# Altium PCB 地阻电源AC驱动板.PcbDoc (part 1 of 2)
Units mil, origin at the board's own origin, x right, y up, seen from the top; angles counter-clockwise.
Board outline 3149.61 x 5118.11 mil, 2 copper layers (Top Layer, Bottom Layer); 154 components, 62 nets, 426 pads, 73 vias.
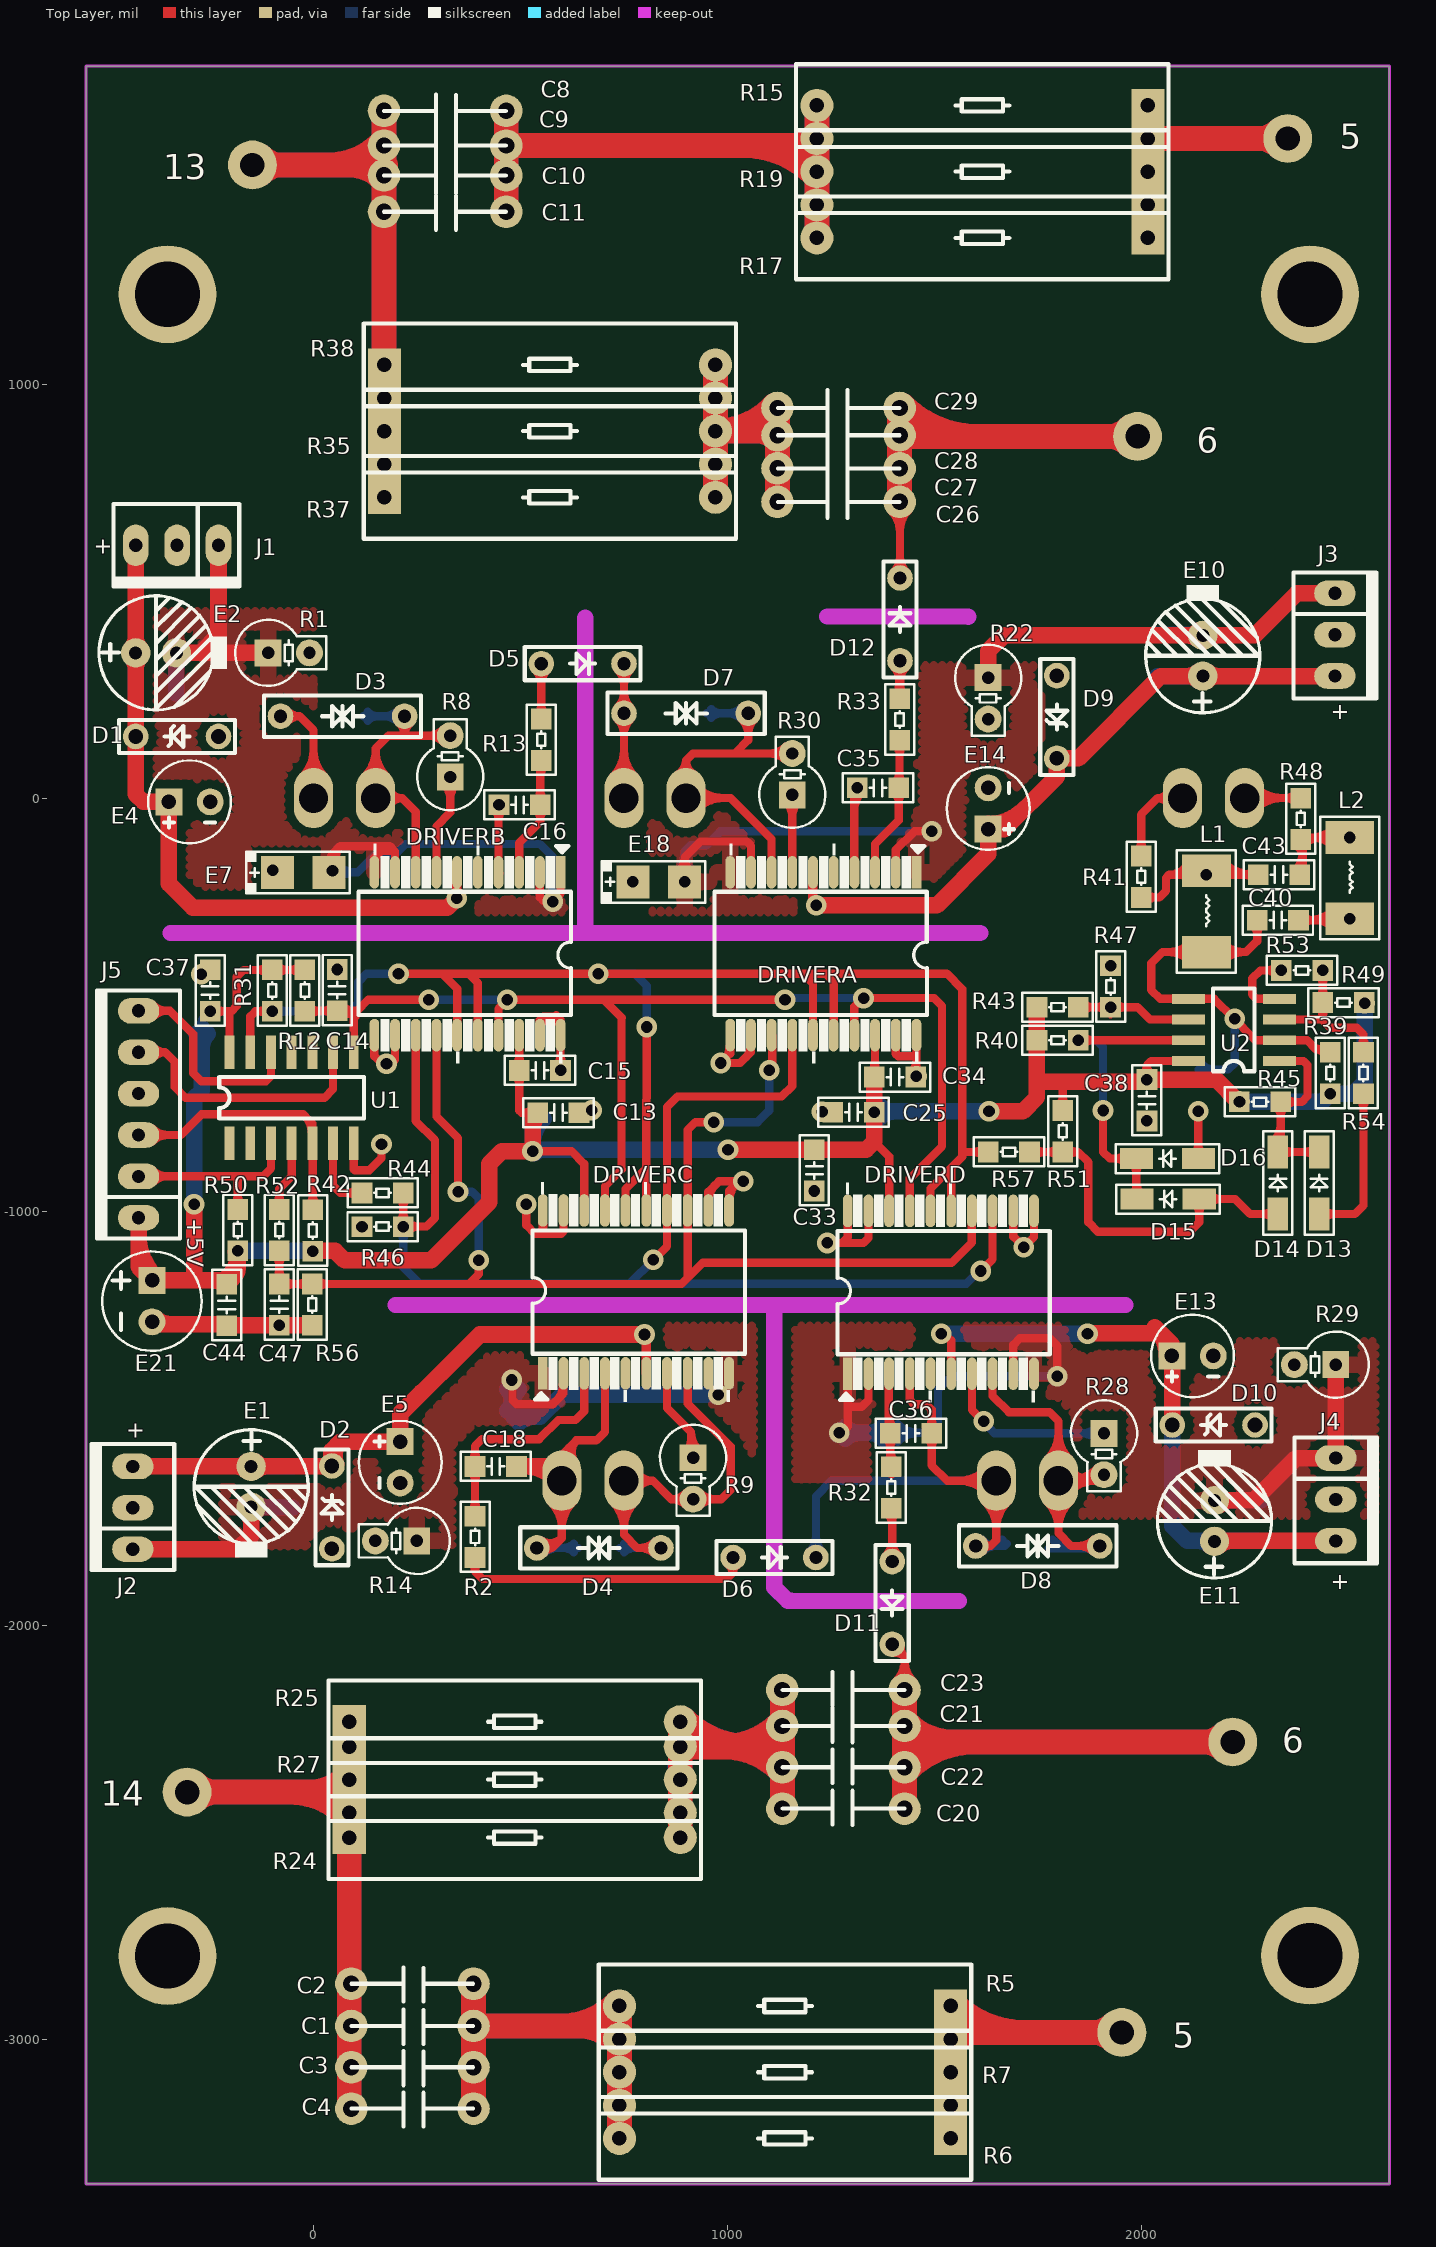
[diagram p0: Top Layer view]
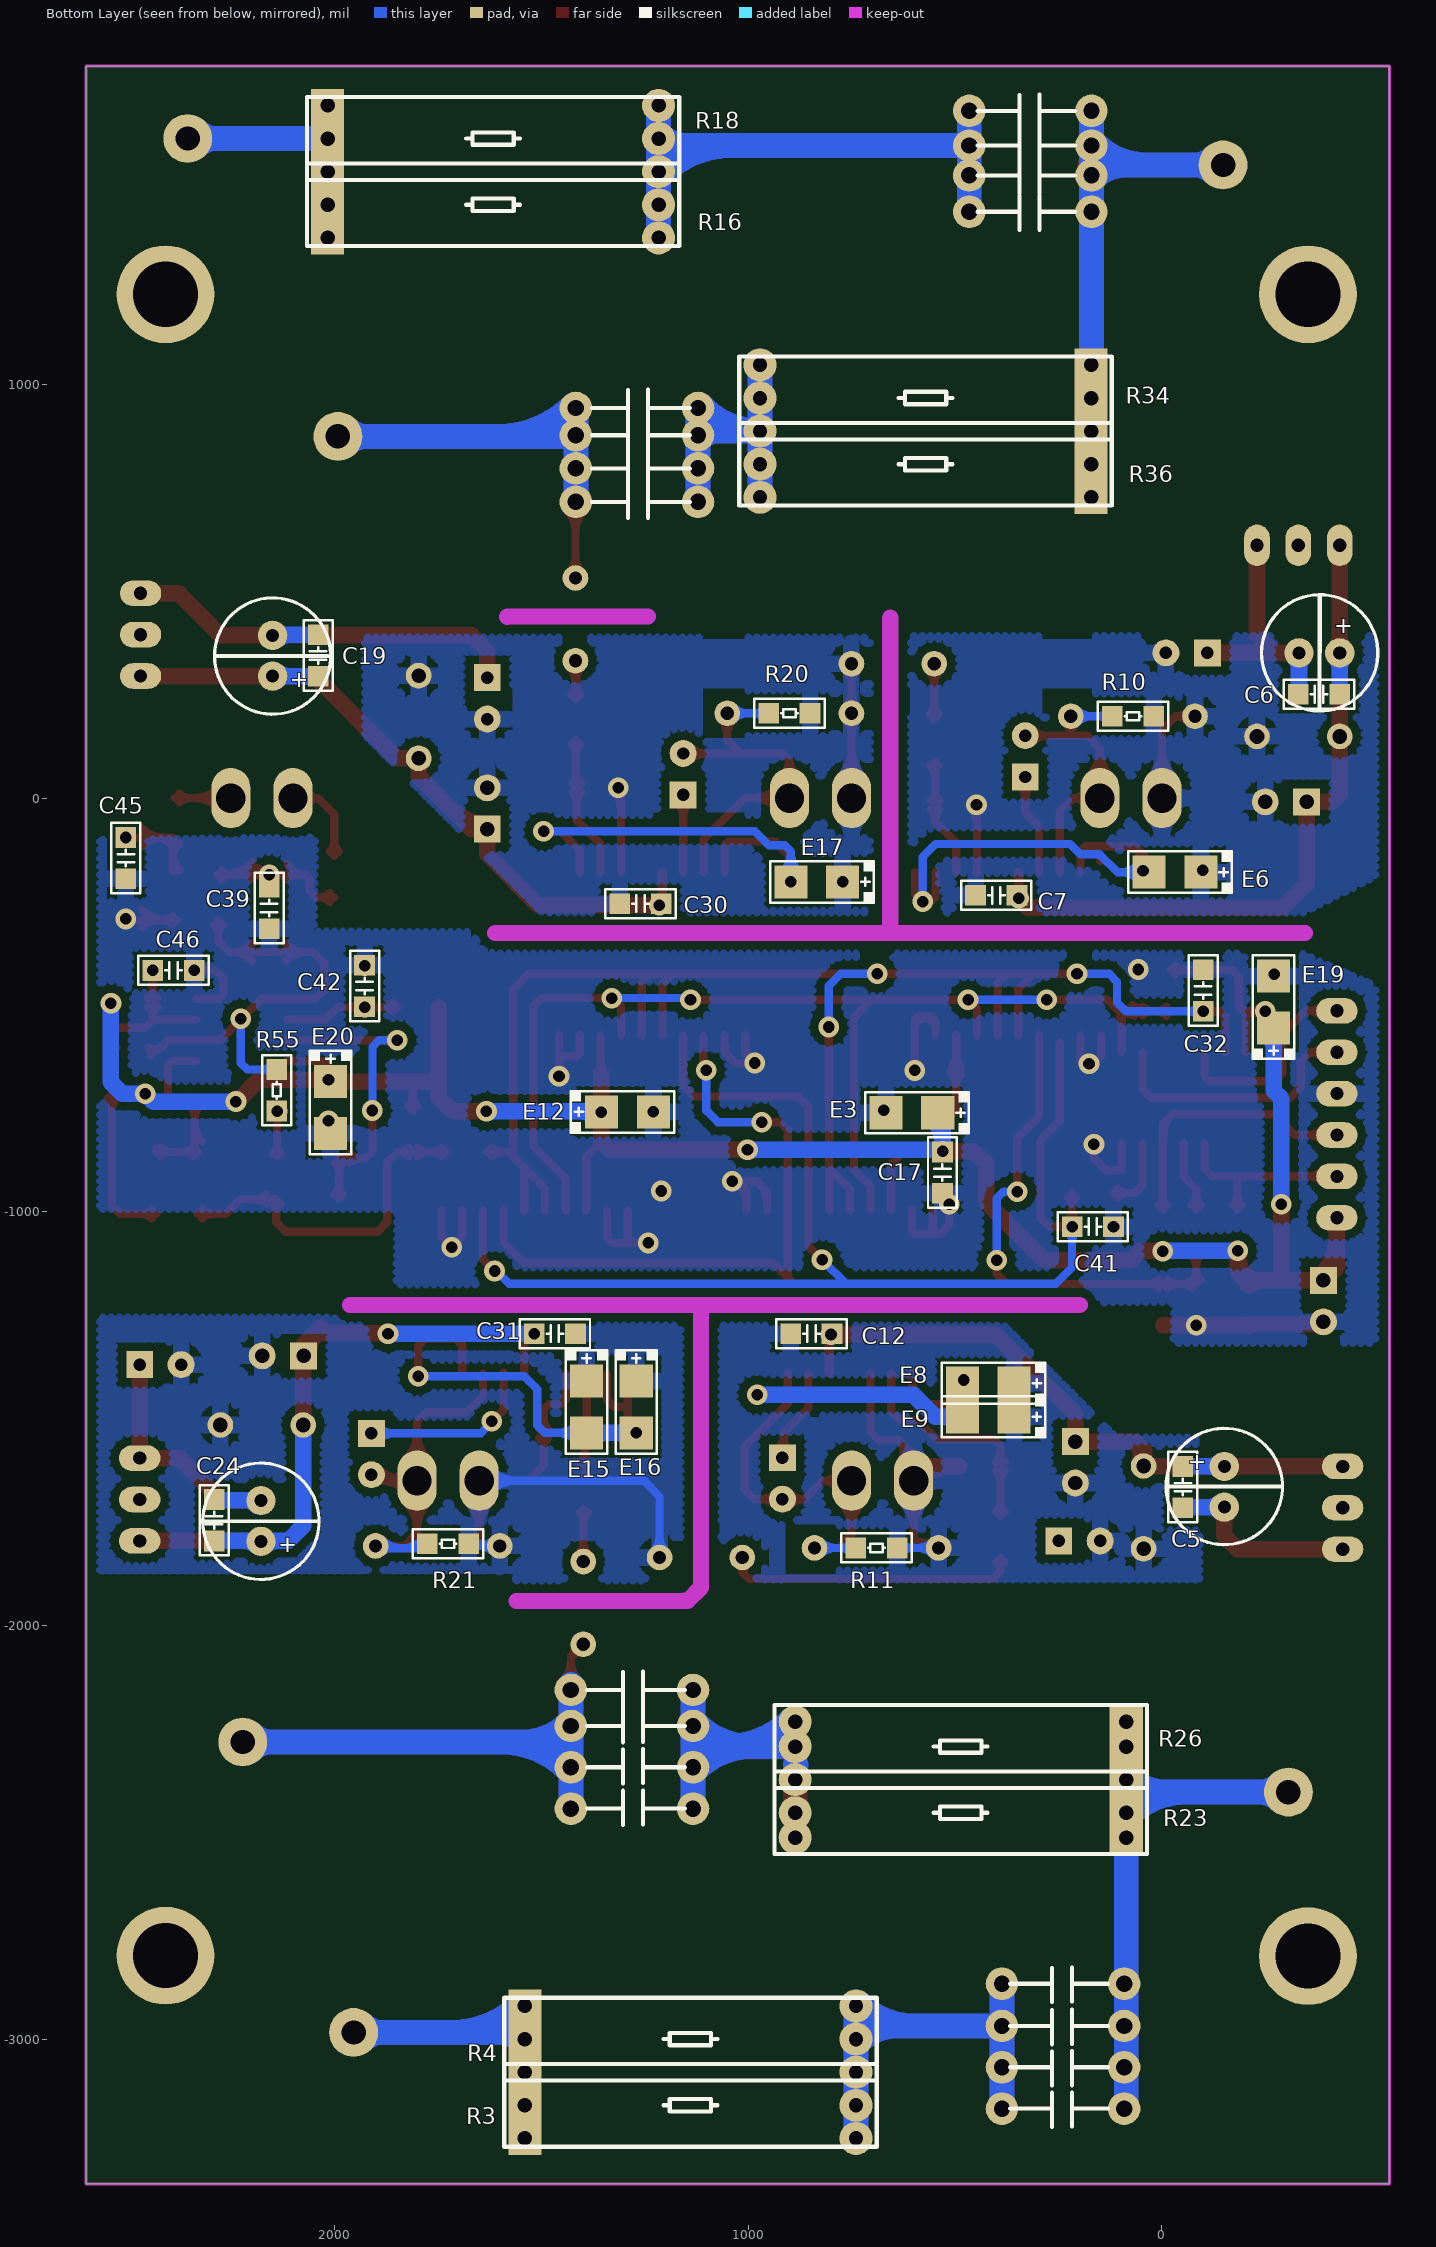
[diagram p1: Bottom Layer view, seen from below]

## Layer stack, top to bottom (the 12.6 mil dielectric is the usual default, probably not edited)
Top Layer: signal copper 1.4
Dielectric: dielectric 12.6, FR-4, Dk 4.8
Bottom Layer: signal copper 1.4

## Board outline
-549.72,-3349.01 2599.88,-3349.01 2599.88,1769.1 -549.72,1769.1

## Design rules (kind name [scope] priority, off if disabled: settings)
Clearance [All] p1: gap=12
ComponentClearance [All] p1 off: gap=10 collisioncheckmode=3 verticalgap=10
HoleSize [All] p1: absolutevalues=TRUE maxlimit=200 minlimit=20 maxpercent=80.000 minpercent=20.000
MaximumViaCount [All] p1: limit=1000
ParallelSegment [All] p1: limit=10000 gap=10
PolygonConnect [All] p1: connectstyle=Relief reliefconductorwidth=40 reliefentries=4 polygonreliefangle="90 Angle"
RoutingVias [All] p1: holewidth=28 width=50 viastyle="Through Hole" minholewidth=20 minwidth=30 maxholewidth=100 maxwidth=200
SolderMaskExpansion [All] p1: expansion=4
TestPointUsage [All] p1: valid=0 allowmultiple=FALSE
Testpoint [All] p1: side=15 testpointundercomponent=TRUE minsize=40 maxsize=100 preferedsize=60 minholesize=0 maxholesize=40 preferedholesize=32 testpointgrid=1 style=1023 order=0123456789
ViasUnderSMD [All] p1: allowed=TRUE
Width Width_1 [InNet('+5V')] p1: maxlimit=50 minlimit=10 preferedwidth=40
Width [All] p2: maxlimit=100 minlimit=10 preferedwidth=20 toplayer_prefwidth=40 minimp=50.000000 maximp=50.000000 favimp=50.000000
17 further rules are at their usual default settings.

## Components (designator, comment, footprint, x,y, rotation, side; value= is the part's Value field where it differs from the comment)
C1 "102/2KV" CP-7.5 91.28,-2967.16 r0 top
C2 "102/2KV" CP-7.5 91.28,-2865.16 r0 top
C3 "102/2KV" CP-7.5 91.28,-3067.16 r0 top
C4 "102/2KV" CP-7.5 91.28,-3167.16 r0 top
C5 "104" 0805C -50.72,-1715.16 r90 bottom
C6 "104" 0805C -329.72,250.99 r180 bottom
C7 "104" 0805C 350.28,-235.16 r0 bottom
C8 "102/2KV" CP-7.5 170.28,1660.84 r0 top
C9 "102/2KV" CP-7.5 170.28,1576.84 r0 top
C10 "102/2KV" CP-7.5 170.28,1504.84 r0 top
C11 "102/2KV" CP-7.5 170.28,1416.84 r0 top
C12 "104" 0805C 797.09,-1294.17 r0 bottom
C13 "104" 0805C 541.71,-760.35 r0 top
C14 "104" 0805C 57.09,-514.17 r90 top
C15 "104" 0805C 496.94,-658.16 r0 top
C16 "100P" 0805C 548.09,-16.17 r180 top
C17 "104" 0805C 530.28,-855.16 r270 bottom
C18 "100P" 0805C 390.28,-1615.16 r0 top
C19 "104" 0805C 2039.09,394.83 r270 bottom
C20 "102/2KV" CP-7.5 1428.28,-2442.16 r180 top
C21 "102/2KV" CP-7.5 1428.28,-2242.16 r180 top
C22 "102/2KV" CP-7.5 1428.28,-2342.16 r180 top
C23 "102/2KV" CP-7.5 1428.28,-2155.16 r180 top
C24 "104" 0805C 2290.28,-1795.16 r90 bottom
C25 "104" 0805C 1354.94,-759.16 r180 top
C26 "102/2KV" CP-7.5 1416.28,715.84 r180 top
C27 "102/2KV" CP-7.5 1416.28,796.84 r180 top
C28 "102/2KV" CP-7.5 1416.28,876.84 r180 top
C29 "102/2KV" CP-7.5 1416.28,942.84 r180 top
C30 "104" 0805C 1210.28,-255.16 r0 bottom
C31 "104" 0805C 1517.09,-1294.17 r180 bottom
C32 "104" 0805C -99.65,-515.16 r90 bottom
C33 "104" 0805C 1210.28,-849.49 r270 top
C34 "104" 0805C 1354.94,-674.16 r0 top
C35 "100P" 0805C 1413.94,24.84 r180 top
C36 "100P" 0805C 1393.94,-1535.16 r0 top
C37 "104" 0805C -249.72,-515.16 r90 top
C38 "104" 0805C 2013.94,-680.16 r270 top
C39 "104" 0805C 2157.54,-315.54 r90 bottom
C40 "104" 0805C 2280.28,-295.01 r0 top
C41 "30P" 0805C 217.05,-1035.59 r180 bottom
C42 "104" 0805C 1926.94,-504.16 r90 bottom
C43 "104" 0805C 2283.28,-185.16 r0 top
C44 "104" 0805C -209.72,-1175.16 r270 top
C45 "104" 0805C 2503.94,-95.16 r270 bottom
C46 "104" 0805C 2438.78,-416.43 r180 bottom
C47 "30P" 0805C -82.91,-1174.17 r270 top
D1 "IN4745" DIODE0.3-0.1 -334.72,154.99 r0 top
D2 "IN4745" DIODE0.3-0.1 50.28,-1709.01 r270 top
D3 "P6KE18CA" DIODE0.3-AC -79.91,197.83 r0 top
D4 "P6KE18CA" DIODE0.3-AC 539.61,-1812.05 r0 top
D5 "ER34-10" DIODE0.2 750.28,324.84 r180 top
D6 "ER34-10" DIODE0.2 1213.94,-1835.16 r180 top
D7 "P6KE18CA" DIODE0.3-AC 750.28,204.84 r0 top
D8 "P6KE18CA" DIODE0.3-AC 1600.15,-1807.2 r0 top
D9 "IN4745" DIODE0.3-0.1 1790.28,190.99 r90 top
D10 "IN4745" DIODE0.3-0.1 2170.28,-1509.01 r0 top
D11 "ER34-10" DIODE0.2 1398.28,-2045.01 r90 top
D12 "ER34-10" DIODE0.2 1417.28,531.84 r270 top
D13 "IN4148" DIODE-SMD0.15 2430.28,-855.16 r270 top
D14 "IN4148" DIODE-SMD0.15 2330.28,-855.16 r270 top
D15 "IN4148" DIODE-SMD0.15 1990.28,-969.01 r0 top
D16 "IN4148" DIODE-SMD0.15 1988.28,-871.16 r0 top
DRIVERA "IGBT driver" SOP20-7.6-1.27 1273.94,-375.16 r270 top locked
DRIVERB "IGBT driver" SOP20-7.6-1.27 413.94,-375.15 r270 top locked
DRIVERC "IGBT driver" SOP20-7.6-1.27 737.09,-1194.17 r90 top locked
DRIVERD "IGBT driver" SOP20-7.6-1.27 1473.94,-1195.16 r90 top locked
E1 "100u/50V" E2.5-7 -150.72,-1615.16 r270 top
E2 "100u/50V" E2.5-7 -429.72,350.99 r0 top
E3 "10uF/16V" 1210E 541.69,-760.35 r0 bottom
E4 "10u/50v" E0.1/R0.1 -349.72,-9.01 r0 top
E5 "10u/50v" E0.1/R0.1 209.28,-1555.16 r270 top
E6 "10uF/16V" 1210E -94.09,-178.98 r0 bottom
E7 "10uF/16V" 1210E -87.4,-179.96 r0 top
E8 "10uF/16V" 1210E 357.09,-1414.17 r0 bottom
E9 "10uF/16V" 1210E 357.28,-1495.16 r0 bottom
E10 "100u/50V" E2.5-7 2148.94,294.84 r90 top
E11 "100u/50V" E2.5-7 2177.28,-1796.01 r90 top
E12 "10uF/16V" 1210E 1353.94,-758.16 r180 bottom
E13 "10u/50v" E0.1/R0.1 2074.28,-1348.01 r0 top
E14 "10u/50v" E0.1/R0.1 1630.28,-75.16 r90 top
E15 "10uF/16V" 1210E 1390.28,-1409.01 r270 bottom
E16 "10uF/16V" 1210E 1270.28,-1409.01 r270 bottom
E17 "10uF/16V" 1210E 771.61,-202.36 r0 bottom
E18 "10uF/16V" 1210E 771.61,-202.36 r0 top
E19 "10uF/16V" 1210E -269.72,-555.16 r90 bottom
E20 "10uF/16V" 1210E 2008.95,-685.14 r270 bottom
E21 "100u/25V" E0.1/R0.12 -390.35,-1165.63 r270 top
J1 "AC驱动电源" CON03 -229.72,610.99 r180 top
J2 "AC驱动电源" CON03 -436.72,-1815.01 r90 top
J3 "AC驱动电源" CON03 2468.28,494.99 r270 top
J4 "AC驱动电源" CON03 2470.28,-1595.01 r270 top
J5 "AC-全桥" CON06 -422.91,-1014.17 r90 top
L1 "10uH" L10UH-SMD 2157.54,-175.54 r270 top
L2 "10uH" L10UH-SMD 2503.94,-95.16 r270 top
R1 "510/1W" RES0.1-1W-STAND -109.72,350.99 r0 top
R2 "510/1W" RES0.1-1W-STAND 249.28,-1795.16 r180 top
R3 "51/2W" RES0.8-2W 1539.28,-3159.01 r180 bottom
R4 "51/2W" RES0.8-2W 1539.28,-2999.01 r180 bottom
R5 "51/2W" RES0.8-2W 1539.28,-2919.01 r180 top
R6 "51/2W" RES0.8-2W 1539.28,-3239.01 r180 top
R7 "51/2W" RES0.8-2W 1539.28,-3079.01 r180 top
R8 "10/1W" RES0.1-1W-STAND 330.28,50.99 r90 top
R9 "10/1W" RES0.1-1W-STAND 917.09,-1594.17 r270 top
R10 "5.1K" 0805R 20.09,197.83 r0 bottom
R11 "5.1K" 0805R 639.61,-1812.05 r0 bottom
R12 "5.1K" 0805R -20.91,-515.17 r90 top
R13 "1.2K" 0805R 550.28,190.99 r270 top
R14 "1.2K" 0805R 390.28,-1835.16 r90 top
R15 "51/2W" RES0.8-2W 2016.28,1673.84 r180 top
R16 "51/2W" RES0.8-2W 2016.28,1433.84 r180 bottom
R17 "51/2W" RES0.8-2W 2016.28,1353.84 r180 top
R18 "51/2W" RES0.8-2W 2016.28,1593.84 r180 bottom
R19 "51/2W" RES0.8-2W 2016.28,1513.84 r180 top
R20 "5.1K" 0805R 850.28,204.84 r0 bottom
R21 "5.1K" 0805R 1675.15,-1802.2 r0 bottom
R22 "510/1W" RES0.1-1W-STAND 1630.28,290.99 r270 top
R23 "51/2W" RES0.8-2W 86.28,-2452.01 r0 bottom
R24 "51/2W" RES0.8-2W 86.28,-2512.01 r0 top
R25 "51/2W" RES0.8-2W 86.28,-2232.01 r0 top
R26 "51/2W" RES0.8-2W 86.28,-2292.01 r0 bottom
R27 "51/2W" RES0.8-2W 86.28,-2372.01 r0 top
R28 "10/1W" RES0.1-1W-STAND 1910.28,-1535.16 r270 top
R29 "510/1W" RES0.1-1W-STAND 2470.28,-1369.01 r180 top
R30 "10/1W" RES0.1-1W-STAND 1156.94,7.84 r90 top
R31 "5.1K" 0805R -99.65,-515.16 r90 top
R32 "1.2K" 0805R 1396.28,-1716.16 r90 top
R33 "1.2K" 0805R 1416.28,239.84 r270 top
R34 "51/2W" RES0.8-2W 171.28,966.84 r0 bottom
R35 "51/2W" RES0.8-2W 171.28,886.84 r0 top
R36 "51/2W" RES0.8-2W 171.28,806.84 r0 bottom
R37 "51/2W" RES0.8-2W 171.28,726.84 r0 top
R38 "51/2W" RES0.8-2W 171.28,1046.84 r0 top
R39 "15K" 0805R 2457.09,-714.17 r90 top
R40 "5.1K" 0805R 1848.09,-585.17 r180 top
R41 "0" 0805R 2000,-140 r270 top
R42 "5.1K" 0805R -1.72,-995.01 r270 top
R43 "15K" 0805R 1748.09,-505.17 r0 top
R44 "180" 0805R 117.09,-954.17 r0 top
R45 "5.1K" 0805R 2337.09,-734.17 r180 top
R46 "15K" 0805R 117.05,-1035.59 r0 top
R47 "470" 0805R 1926.09,-505.17 r90 top
R48 "0" 0805R 2385.43,0 r270 top
R49 "3K" 0805R 2438.78,-494.17 r0 top
R50 "5.1K" 0805R -182.91,-994.17 r270 top
R51 "5.1K" 0805R 1810.28,-755.16 r270 top
R52 "180" 0805R -82.91,-994.17 r270 top
R53 "30K" 0805R 2338.78,-416.43 r0 top
R54 "30K" 0805R 2537.09,-714.17 r90 top
R55 "30K" 0805R 2139.28,-656.01 r270 bottom
R56 "15K" 0805R -2.91,-1274.17 r90 top
R57 "5.1K" 0805R 1730.28,-855.16 r180 top
U1 "74HC04" SOP14 -202.91,-834.17 r90 top
U2 "LM358" SOP08 2333.94,-635.16 r180 top

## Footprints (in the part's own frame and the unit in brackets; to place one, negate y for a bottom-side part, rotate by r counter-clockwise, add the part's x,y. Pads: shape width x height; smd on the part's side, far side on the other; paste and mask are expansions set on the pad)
0805C [mil]
  rect 50x50 smd: 1(0,0) 2(100,0)
  silkscreen extent -35,-35 135,35
0805R [mil]
  rect 50x50 smd: 1(0,0) 2(100,0)
  silkscreen extent -35,-35 135,35
1210E [mil]
  rect 80x80 smd: 1(0,0) 2(125,0)
  silkscreen extent -75,-50 175,50
CON03 [mil]
  oval 62x100 hole 32: 1(0,0) 2(100,0) 3(200,0)
  silkscreen extent -50,-100 254,100
CON06 [mil]
  oval 62x100 hole 32: 1(0,0) 2(100,0) 3(200,0) 4(300,0) 5(400,0) 6(500,0)
  silkscreen extent -50,-100 549,100
CP-7.5 [mm]
  round 2 hole 1: 1(0,0) 2(7.5,0)
  silkscreen extent 0,-1.1 7.47,1
DIODE0.2 [mil]
  round 62 hole 32: 1(200,0) 2(0,0)
  silkscreen extent -40,-40 240,40
DIODE0.3-0.1 [mm]
  round 1.575 hole 0.9: 1(2.667,-0.152) 2(-2.413,-0.152)
  silkscreen extent -3.43,-1.17 3.68,0.86
DIODE0.3-AC [mil]
  round 62 hole 32: 1(0,0) 2(300,0)
  silkscreen extent -40,-50 340,50
DIODE-SMD0.15 [mil]
  rect 80x50 smd: 1(150,0) 2(0,0)
  silkscreen extent -50,-35 200,35
E0.1/R0.1 [mil]
  rect 65x65 hole 35: 1(0,0)
  round 65 hole 35: 2(100,0)
  silkscreen extent -50,-100 150,100
E0.1/R0.12 [mil]
  rect 65x65 hole 35: 1(0,0)
  round 65 hole 35: 2(100,0)
  silkscreen extent -70,-120 170,120
E2.5-7 [mm]
  round 1.8 hole 0.8: 1(0,0) 2(2.5,0)
  silkscreen extent -2.25,-3.5 5.6,3.5
L10UH-SMD [mm] "贴片电感"
  rect 2x3 smd: 1(0,0) 2(5,0)
  silkscreen extent -1.27,-1.8 6.26,1.8
RES0.1-1W-STAND [mil]
  rect 65x65 hole 30: 1(0,0)
  round 65 hole 30: 2(100,0)
  silkscreen extent -80,-80 140,80
RES0.8-2W [mil]
  rect 80x80 hole 35: 1(0,0)
  round 80 hole 35: 2(800,0)
  silkscreen extent -50,-100 850,100
SOP08 [mil]
  rect 80x24 smd: 1(0,0) 2(0,-50) 3(0,-100) 4(0,-150) 5(220,-150) 6(220,-100) 7(220,-50) 8(220,0)
  silkscreen extent 60,-175 160,25
SOP14 [mil]
  rect 80x24 smd: 1(0,0) 2(0,-50) 3(0,-100) 4(0,-150) 5(0,-200) 6(0,-250) 7(0,-300) 8(220,-300) 9(220,-250) 10(220,-200) 11(220,-150) 12(220,-100) 13(220,-50) 14(220,0)
  silkscreen extent 60,-325 160,25
SOP20-7.6-1.27 [mm]
  rect 2x0.6 smd: 1(-4.978,4.648)
  oval 2x0.6 smd: 2(-4.978,3.378) 3(-4.978,2.108) 4(-4.978,0.838) 5(-4.978,-0.432) 6(-4.978,-1.702) 7(-4.978,-2.972) 8(-4.978,-4.242) 9(-4.978,-5.512) 10(-4.978,-6.782) 11(5.022,-6.782) 12(5.022,-5.512) 13(5.022,-4.242) 14(5.022,-2.972) 15(5.022,-1.702) 16(5.022,-0.432) 17(5.022,0.838) 18(5.022,2.108) 19(5.022,3.378) 20(5.022,4.648)
  silkscreen extent -6.74,-7.75 6.77,5.29

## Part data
C1 C2 C3 C4 C8 C9 C10 C11 C20 C21 C22 C23 C26 C27 C28 C29: library part Cap2, "CBB电容"
C5 C6 C7 C12 C13 C14 C15 C16 C17 C18 C19 C24 C25 C30 C31 C32 C33 C34 C35 C36 C37 C38 C39 C40 C41 C42 C43 C44 C45 C46 C47: library part Cap, "贴片电容"
D1 D2 D9 D10: library part Diode5, "贴片稳压管"
D3 D4 D7 D8: library part "D TVS", "TVS管"
D5 D6 D11 D12: library part Diode2, "贴片二极管"
D13 D14: library part DIODE7
D15 D16: library part Diode1, "二极管"
DRIVERA: "单个IGBT驱动"
E1 E2 E4 E5 E10 E11 E13 E14: library part "Cap Pol", "电解电容"
E3: library part "Cap Pol", "贴片电解电容"
E6 E7 E8 E9 E12 E15 E16 E17 E18 E19 E20 E21: library part "Cap Pol3", "贴片电解电容"
J1 J2 J3 J4: library part CON3, "接插件，3针"
J5: library part CON6, "接插件，6针"
L1 L2: library part Inductor1, "贴片电感"
R1 R2 R8 R9 R10 R11 R12 R13 R14 R20 R21 R28 R29 R30 R31 R32 R33 R39 R40 R41 R42 R43 R44 R45 R46 R47 R48 R49 R50 R51 R52 R53 R54 R55 R56 R57: library part RES2, "贴片电阻"
R3 R4 R5 R6 R7 R15 R16 R17 R18 R19 R22 R23 R24 R25 R26 R27 R34 R35 R36 R37 R38: library part RES1, "金属膜电阻"
U1: "6通道反相器"
U2: "双运放"

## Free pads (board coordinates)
  round 118.11 hole 59.06: 0(1953.28,-2983.01) 0(2221.28,-2281.01) 0(2354.28,1593.99) 1(1991.28,873.99) 2(-305.72,-2402.16) 3(-147.72,1529.99)
  oval 94.49x145.67 hole 70.87: 0(2250,0) 1(600,-1649.61) 2(750,-1649.61) 3(1650,-1649.61) 4(1800,-1649.61) 8(2100,0) 9(900,0) 10(750,0) 11(150,0) 12(0,0)
  round 236.22 hole 157.48: 3(-352.87,-2798.31) 3(-352.87,1217.44) 3(2407.95,-2797.32) 3(2407.95,1217.44)

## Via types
v1: diameter 50, hole 28, Top Layer to Bottom Layer, 54 vias
v2: diameter 50, hole 27.99, Top Layer to Bottom Layer, 19 vias

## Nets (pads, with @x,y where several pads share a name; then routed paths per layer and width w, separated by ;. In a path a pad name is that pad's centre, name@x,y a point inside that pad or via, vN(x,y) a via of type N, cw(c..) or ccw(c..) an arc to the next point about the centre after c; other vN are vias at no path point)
+5V: C13.1 C15.1 C17.1 C25.1 C33.1 C34.1 C37.1 C38.1 C44.1 DRIVERA.18 DRIVERB.18 DRIVERC.18 DRIVERD.18 E3.1 E12.1 E19.1 E20.1 E21.1 J5.1 R12.2 R31.2 R39.1 R40.2 R42.2 R43.1 R45.2 R49.2 R50.2 R51.1 U1.14 U2.8 | length 7444.8
  Top Layer w20: E21.1@-377.85,-1153.13 E21.1@-375.35,-1155.63 ; v2(-249.72,-515.16) -213.87,-515.16 ; C37.1@-239.04,-525.69 cw(c-213.88,-550.49) -213.88,-515.16 ; C37.1@-239.04,-504.63 ccw(c-213.88,-479.82) -213.88,-515.16 ; U1.14@-202.91,-614.17 -202.91,-526.12 -213.87,-515.16 ; R31.2@-110.25,-425.76 ccw(c-135.86,-451.37) -135.86,-415.16 ccw(c-135.86,-378.94) R31.2@-110.25,-404.55 ; R31.2@-89.04,-425.76 cw(c-63.43,-451.37) -63.43,-415.16 cw(c-63.43,-378.94) R31.2@-89.04,-404.55 ; -57.16,-415.16 cw(c-57.16,-451.42) R12.2@-31.52,-425.78 ; -57.09,-415.16 ccw(c-57.09,-379) R12.2@-31.52,-404.57 ; R12.2@-20.91,-415.17 R31.2@-99.65,-415.16 -168.87,-415.16 -185.72,-432.01 -185.72,-502.31 -198.57,-515.16 -213.87,-515.16 ; C15.1@486.33,-668.76 cw(c460.72,-694.37) 496.94,-694.37 cw(c533.15,-694.37) C15.1@507.54,-668.76 ; C15.1@486.33,-647.55 ccw(c460.72,-621.94) 496.94,-621.94 ccw(c533.15,-621.94) C15.1@507.54,-647.55 ; C15.1@493.94,-661.16 C15.1@496.94,-658.16 ; DRIVERB.18@496.94,-572.85 C15.1@496.94,-658.16 ; v1(529.28,-853.16) 623.43,-853.16 654.09,-883.82 DRIVERC.18@654.09,-996.47 ; C13.1@531.1,-770.95 ccw(c505.5,-796.56) 505.5,-760.35 ccw(c505.5,-724.13) C13.1@531.1,-749.74 ; C13.1@541.71,-760.35 502.47,-760.35 496.94,-754.82 C15.1@496.94,-658.16 ; C34.1@1344.33,-663.55 ccw(c1313.9,-633.12) 1356.94,-633.12 ; 1354.94,-830.16 1390.94,-866.16 DRIVERD.18@1390.94,-997.46 ; C34.1@1354.94,-674.16 C34.1@1356.94,-672.16 ; C34.1@1356.94,-674.16 C34.1@1356.94,-672.16 ; 1356.94,-642.77 ccw(c1386.32,-642.77) C34.1@1365.54,-663.55 ; DRIVERA.18@1356.94,-572.86 C34.1@1356.94,-672.16 ; R51.1@1799.67,-744.55 ccw(c1774.06,-718.94) 1810.28,-718.94 ccw(c1846.49,-718.94) R51.1@1820.88,-744.55 ; 1806.3,-685.14 1810.28,-689.12 R51.1@1810.28,-755.16 ; C38.1@2003.67,-669.22 ccw(c1981.39,-645.5) 2013.94,-645.5 ; C38.1@2017.28,-676.82 v1(2013.94,-680.16) 2013.94,-645.5 ; C38.1@2024.2,-669.22 cw(c2046.48,-645.5) 2013.94,-645.5 ; U2.8@2113.94,-635.16 2024.28,-635.16 2013.94,-645.5
  Top Layer w40: -422.91,-1056.85 ccw(c-281.57,-1056.85) E21.1@-381.52,-1156.79 ; J5.1@-422.91,-1014.17 -422.91,-1132.99 -390.35,-1165.55 -288.72,-1165.55 ; v2(-288.72,-981.16) -288.72,-1165.55 ; -244.99,-1165.55 cw(c-244.99,-1210.42) C44.1@-213.26,-1178.69 ; C44.1@-213.26,-1171.62 ccw(c-286.52,-1098.36) R50.2@-182.91,-1098.36 ; C44.1@-211.28,-1170.4 ccw(c-224.05,-1131.3) -182.91,-1131.3 ; C44.1@-204.72,-1175.16 cw(c-151.5,-1175.16) -189.13,-1137.52 ; -198.6,-1146.99 ccw(c-232.66,-1112.93) R50.2@-187.59,-1095.94 ; v1(-182.91,-1094.17) -182.91,-1131.3 ; R42.2@4.29,-1094.17 52.05,-1094.17 75.08,-1117.2 283.94,-1117.2 424.28,-976.87 424.28,-884.16 455.28,-853.16 v1(529.28,-853.16) 529.28,-772.78 C13.1@541.71,-760.35 ; C15.1@496.94,-658.16 C15.1@500.47,-661.69 ; 529.28,-802.43 cw(c583.8,-802.43) C13.1@545.24,-763.88 ; v1(1001.46,-849.49) C33.1@1210.28,-849.49 1335.61,-849.49 1354.94,-830.16 v1(1354.94,-759.16) C34.1@1354.94,-674.16 ; v1(1632.36,-756.97) 1714.24,-756.97 1748.09,-723.12 R40.2@1748.09,-585.17 ; R40.2@1747.4,-585.17 1747.4,-505.86 R43.1@1748.09,-505.17 ; 1748.22,-685.14 1806.3,-685.14 C38.1@2008.95,-685.14 ; v1(2013.94,-680.16) 2181.61,-680.16 2234.43,-732.97 2237.09,-732.97 2237.68,-732.97 2238.29,-732.97 R45.2@2240.63,-735.31 ; -288.72,-1165.55 -217.16,-1165.55 -182.91,-1131.3
  Bottom Layer w20: E19.1@-269.72,-555.16 -269.72,-535.16 v2(-249.72,-515.16)
  Bottom Layer w40: v2(-288.72,-981.16) -288.72,-726.16 -269.72,-707.16 E19.1@-269.72,-555.16 ; E19.1@-283.87,-569.3 cw(c-318.01,-603.44) -269.72,-603.44 cw(c-221.44,-603.44) E19.1@-255.58,-569.3 ; v1(-182.91,-1094.17) -2.56,-1094.17 v1(-1.72,-1095.01) ; C17.1@529.28,-838.62 cw(c619.95,-838.62) E3.1@555.84,-774.5 ; C17.1@530.28,-855.16 529.28,-854.16 v1(529.28,-853.16) 529.28,-772.78 E3.1@541.69,-760.35 ; C17.1@533.81,-858.69 cw(c556.03,-880.91) 556.03,-849.49 ; C17.1@535.95,-849.49 v1(1001.46,-849.49) v1@997.79,-853.16 ; v1(1354.94,-759.16) 1357.13,-756.97 v1(1632.36,-756.97) ; E12.1@1368.08,-772.3 cw(c1405.09,-809.31) 1405.09,-756.97 ; E12.1@1368.08,-744.01 ccw(c1399.35,-712.74) 1399.35,-756.97 ; v1(2237.68,-733.35) 2437.91,-733.35 v2(2457.09,-714.17) 2512.76,-714.17 2539.84,-687.09 v2(2539.84,-496.14)
+24V1: C19.2 C30.1 D9.2 DRIVERA.6 E10.1 E14.1 J3.3 | length 2016.8
  Top Layer w23: v1@1205.2,-268.78 1206.94,-267.04 1206.94,-259.16 DRIVERA.6@1206.94,-179.16
  Top Layer w40: v1(1214.82,-259.16) 1506.28,-259.16 1630.28,-135.16 E14.1@1630.28,-75.16 1669.09,-75.16 1796.26,52.01 D9.2@1796.26,95.99 1848.28,95.99 2047.13,294.84 E10.1@2148.94,294.84 ; E14.1@1630.28,-62.66 ccw(c1630.28,61.24) 1717.88,-26.37 ; E10.1@2138.02,283.93 ccw(c2111.68,257.58) 2111.68,294.84 ccw(c2111.68,332.1) E10.1@2138.02,305.76 ; E10.1@2149.09,294.99 J3.3@2468.28,294.99 ; E10.1@2159.85,283.93 cw(c2186.56,257.22) 2186.56,294.99 ; E10.1@2159.85,305.76 ccw(c2185.83,331.74) 2185.83,294.99
  Bottom Layer w40: C19.2@2039.09,294.83 E10.1@2148.94,294.84 ; E10.1@2138.02,283.93 ccw(c2111.68,257.58) 2111.68,294.84 ccw(c2111.68,332.1) E10.1@2138.02,305.76
+24V2: C6.2 C7.1 D1.2 DRIVERB.6 E2.1 E4.1 J1.3 | length 1958.8
  Top Layer w23: v1(345.95,-242.2) 345.95,-180.15 DRIVERB.6@346.94,-179.15 ; v1@346.94,-250.09 v1@349.32,-252.46
  Top Layer w40: E2.1@-440.64,340.08 cw(c-466.98,313.73) -429.72,313.73 cw(c-392.47,313.73) E2.1@-418.81,340.08 ; E2.1@-440.64,361.91 ccw(c-466.98,388.25) -429.72,388.25 ccw(c-392.47,388.25) E2.1@-418.81,361.91 ; J1.3@-429.72,610.99 E2.1@-429.72,350.99 D1.2@-429.72,149.01 -429.72,8.99 -411.72,-9.01 E4.1@-349.72,-9.01 -349.72,-206.84 -291.72,-264.84 323.31,-264.84 v1(345.95,-242.2)
  Bottom Layer w40: E2.1@-440.64,340.08 cw(c-466.98,313.73) -429.72,313.73 cw(c-392.47,313.73) E2.1@-418.81,340.08 ; C6.2@-429.72,250.99 E2.1@-429.72,350.99
+24V3: C5.2 C12.1 D2.2 DRIVERC.6 E1.1 E5.1 J2.3 | length 1932.5
  Top Layer w23: v1(799.69,-1296.34) 804.09,-1300.74 DRIVERC.6@804.09,-1390.17
  Top Layer w40: J2.3@-436.57,-1615.16 E1.1@-150.72,-1615.16 D2.2@43.14,-1615.16 ; E1.1@-161.64,-1626.07 ccw(c-187.98,-1652.42) -187.98,-1615.16 ccw(c-187.98,-1577.9) E1.1@-161.64,-1604.24 ; E1.1@-139.81,-1626.07 cw(c-113.47,-1652.42) -113.47,-1615.16 cw(c-113.47,-1577.9) E1.1@-139.81,-1604.24 ; D2.2@43.14,-1614.01 43.14,-1577.14 65.13,-1555.16 ; D2.2@54.43,-1609.74 cw(c100.36,-1590.4) 65.12,-1555.16 ; 260.28,-1436.16 209.28,-1487.16 209.28,-1489.16 ; v1(799.69,-1296.34) 402.09,-1296.34 209.28,-1489.16 ; 65.13,-1555.16 E5.1@209.28,-1555.16 209.28,-1489.16
  Bottom Layer w40: E1.1@-150.72,-1615.16 C5.2@-50.72,-1615.16 ; E1.1@-139.81,-1626.07 cw(c-113.47,-1652.42) -113.47,-1615.16 cw(c-113.47,-1577.9) E1.1@-139.81,-1604.24
+24V4: C24.1 C31.1 D10.2 DRIVERD.6 E11.1 E13.1 J4.3 | length 1821.9
  Top Layer w20: v1@1522.13,-1291.42 1540.94,-1310.23 DRIVERD.6@1540.94,-1391.16
  Top Layer w40: v1@1871.49,-1293.01 2047.28,-1293.01 2074.28,-1320.01 E13.1@2074.28,-1348.01 ; 2033.28,-1279.01 cw(c1964.48,-1347.81) E13.1@2061.78,-1347.98 ; E13.1@2065.44,-1356.85 cw(c2041.68,-1380.6) 2075.28,-1380.6 ; D10.2@2075.28,-1514.99 E13.1@2075.28,-1349.01 ; E11.1@2177.28,-1796.01 2178.28,-1795.01 J4.3@2470.28,-1795.01 ; E11.1@2188.19,-1806.92 cw(c2216.95,-1835.68) 2216.95,-1795.01
  Bottom Layer w23: v1@1863.66,-1287.48 v1@1867.6,-1291.42
  Bottom Layer w40: C31.1@1524.87,-1294.16 v1(1870.34,-1294.16) ; D10.2@2075.28,-1514.99 2075.28,-1759.01 2111.43,-1795.16 2177.28,-1795.16 C24.1@2280.28,-1795.16 ; 2137.96,-1795.16 cw(c2137.96,-1835.32) E11.1@2166.36,-1806.92 ; E11.1@2188.19,-1806.92 cw(c2216.59,-1835.32) 2216.59,-1795.16
  other v1: 1517.09,-1294.17
/FLT: C32.1 DRIVERA.15 DRIVERA.16 DRIVERB.15 DRIVERB.16 DRIVERC.15 DRIVERC.16 DRIVERD.15 DRIVERD.16 R31.1 R57.2 U1.13 | length 4227.9
  Top Layer w20: U1.13@-152.91,-614.17 -152.91,-527.5 -140.57,-515.16 v1(-99.65,-515.16) ; R31.1@-110.25,-525.76 ccw(c-135.86,-551.37) -135.86,-515.16 ccw(c-135.86,-478.94) R31.1@-110.25,-504.55 ; v1(205.28,-424.16) 314.28,-424.16 ; DRIVERB.15@346.94,-572.85 346.94,-460.5 314.28,-427.83 314.28,-424.16 ; DRIVERB.16@396.94,-572.85 396.94,-446.82 374.28,-424.16 ; DRIVERC.16@754.09,-996.47 754.09,-944.51 798.44,-900.16 804.09,-900.16 ; DRIVERC.15@804.09,-996.47 804.09,-900.16 ; v2(805.28,-553.16) 804.09,-900.16 ; DRIVERA.15@1206.94,-572.86 1206.94,-447.82 1183.28,-424.16 ; DRIVERA.16@1256.94,-572.86 1256.94,-443.82 1237.28,-424.16 ; DRIVERD.16@1490.94,-997.46 1490.94,-943.5 1540.94,-893.5 ; DRIVERD.15@1540.94,-997.46 1540.94,-893.5 ; 1568.4,-855.16 R57.2@1630.28,-855.16 ; R57.2@1619.67,-865.76 ccw(c1594.06,-891.37) 1594.06,-855.16 ccw(c1594.06,-818.94) R57.2@1619.67,-844.55 ; 314.28,-424.16 374.28,-424.16 ; 374.28,-424.16 v2(688.28,-424.16) 1183.28,-424.16 ; 1183.28,-424.16 1237.28,-424.16 ; 1237.28,-424.16 1530.28,-424.16 1567.4,-461.28 1567.4,-867.03 1540.94,-893.5
  Bottom Layer w20: v1(-99.65,-515.16) 87.13,-515.16 108.28,-494.01 108.28,-444.01 128.13,-424.16 v1(205.28,-424.16) ; C32.1@-89.04,-525.76 cw(c-63.43,-551.37) -63.43,-515.16 cw(c-63.43,-478.94) C32.1@-89.04,-504.55 ; v2(688.28,-424.16) 775.13,-424.16 805.28,-454.31 v2(805.28,-553.16) v2@806.28,-552.16
/RST: C14.1 DRIVERA.17 DRIVERB.17 DRIVERC.17 DRIVERD.17 R12.1 U1.8 | length 3258
  Top Layer w20: R12.1@-10.31,-525.78 cw(c17.71,-553.8) 17.71,-514.17 ; R12.1@-10.31,-504.57 ccw(c12.89,-481.37) 12.89,-514.17 ; R12.1@-2.91,-514.17 C14.1@52.64,-514.17 ; C14.1@46.48,-524.78 ccw(c20.87,-550.39) 20.87,-514.17 ccw(c20.87,-477.96) C14.1@46.48,-503.57 ; C14.1@54.1,-510.16 cw(c68.01,-528.87) 84.49,-512.39 ; C14.1@54.86,-511.95 C14.1@52.64,-514.17 ; C14.1@55.42,-509.46 cw(c66.24,-540.13) 89.23,-517.13 ; C14.1@66.03,-526.21 cw(c81.97,-547.66) 100.87,-528.77 ; C14.1@67.69,-524.78 cw(c93.3,-550.39) 93.3,-514.17 cw(c93.3,-477.96) C14.1@67.69,-503.57 ; C14.1@69.28,-522.9 cw(c86.27,-535.07) 86.27,-514.17 ; C14.1@69.28,-505.44 ccw(c86.27,-493.28) 86.27,-514.17 ; C14.1@70.77,-500.49 66.91,-504.35 C14.1@57.09,-514.17 ; U1.8@97.09,-614.17 97.09,-524.98 86.28,-514.17 ; v2(278.12,-487.32) 131.98,-487.32 105.13,-514.17 86.28,-514.17 ; DRIVERB.17@446.94,-572.85 446.94,-508.75 v2(468.4,-487.28) 701.28,-487.28 ; DRIVERC.17@704.09,-996.47 704.09,-937.94 744.71,-897.32 ; 744.28,-896.76 744.28,-530.28 ; 744.28,-530.16 744.28,-530.28 ; 744.71,-530.72 744.28,-530.28 ; v2(1139.28,-487.28) 701.28,-487.28 ; DRIVERA.17@1306.94,-572.86 1306.94,-503.65 v2@1327.24,-483.35 ; v2(1329.21,-483.35) 1499.79,-483.35 1518.94,-502.5 1518.94,-841.5 1442.28,-918.16 1440.94,-918.16 DRIVERD.17@1440.94,-997.46 ; C14.1@52.64,-514.17 C14.1@57.09,-514.17 ; C14.1@57.09,-514.17 86.28,-514.17 ; 701.28,-487.28 744.28,-530.28
  Bottom Layer w20: v2@282.28,-483.16 278.15,-487.28 v2(468.4,-487.28) ; v2(1139.28,-487.28) 1143.21,-483.35 v2(1329.21,-483.35)
ALARM: J5.6 U1.12 | length 588.4
  Top Layer w20: J5.6@-422.91,-514.17 -346.85,-514.17 -290.87,-570.16 -290.87,-664.87 -271.56,-684.17 -115.17,-684.17 -102.91,-671.92 U1.12@-102.91,-614.17 ; J5.6@-389.06,-529.02 cw(c-353.21,-564.87) -353.21,-514.17 cw(c-353.21,-463.47) J5.6@-389.06,-499.32
DRIVERA: D7.2 DRIVERA.8 pad.9 R20.2 R30.2 | length 1420.3
  Top Layer w20: pad.9@880.84,57.53 ccw(c860.52,91.38) 900,91.38 ; pad.9@892.21,-3.03 pad.9@892.21,0 ; pad.9@919.16,57.53 cw(c939.48,91.38) 900,91.38 ; pad.9@926.34,-26.34 cw(c989.92,-89.91) 989.92,0 cw(c989.92,89.92) pad.9@926.34,26.34 ; D7.2@1035.43,189.99 cw(c999.58,154.14) 1050.28,154.14 cw(c1100.97,154.14) D7.2@1065.13,189.99 ; D7.2@1050.28,204.84 1050.28,139.99 1019.28,108.99 1019.28,107.84 ; DRIVERA.8@1106.94,-179.16 1106.94,-98.82 1008.12,0 pad.9@900,0 900,91.38 ; R30.2@1141.03,91.93 ccw(c1102.62,53.52) 1102.62,107.84 ccw(c1102.62,162.16) R30.2@1141.03,123.75 ; R30.2@1156.94,107.84 1019.28,107.84 ; 900,91.38 916.46,107.84 1019.28,107.84
  Bottom Layer w20: R20.2@950.28,204.84 D7.2@1050.28,204.84 ; R20.2@960.88,194.24 cw(c986.49,168.63) 986.49,204.84 cw(c986.49,241.06) R20.2@960.88,215.45 ; D7.2@1035.43,189.99 ccw(c999.58,154.14) 999.58,204.84 ccw(c999.58,255.54) D7.2@1035.43,219.69
DRIVERB: D3.2 DRIVERB.8 pad.11 R8.2 R10.2 | length 1226.7
  Top Layer w20: pad.11@123.66,51.93 ccw(c60.09,115.51) 150,115.51 ccw(c239.92,115.51) pad.11@176.34,51.93 ; pad.11@182.35,-18.45 cw(c214.12,-36.56) 214.12,0 ; pad.11@182.35,18.45 ccw(c214.12,36.57) 214.12,0 ; D3.2@206.17,182.1 cw(c178.79,151.18) 220.09,151.18 ; D3.2@220.09,197.83 220.09,151.18 ; D3.2@234.01,182.1 ccw(c261.39,151.18) 220.09,151.18 ; DRIVERB.8@246.94,-179.15 246.94,-32.82 214.12,0 ; R8.2@314.37,135.08 ccw(c275.96,96.67) 275.96,150.99 ccw(c275.96,205.31) R8.2@314.37,166.9 ; R8.2@330.28,150.99 220.28,150.99 ; 214.12,0 pad.11@150,0 150,119.72 181.28,150.99 220.28,150.99 ; 220.09,151.18 220.28,150.99
  Bottom Layer w20: R10.2@120.09,197.83 D3.2@220.09,197.83 ; R10.2@130.69,187.22 cw(c156.3,161.61) 156.3,197.83 cw(c156.3,234.04) R10.2@130.69,208.43 ; D3.2@205.24,182.98 ccw(c169.39,147.13) 169.39,197.83 ccw(c169.39,248.53) D3.2@205.24,212.68
DRIVERC: D4.2 DRIVERC.8 pad.2@750,-1649.61 R9.2 R11.2 | length 1567.6
  Top Layer w20: pad.2@723.66,-1701.53 cw(c660.09,-1765.11) 750,-1765.11 cw(c839.92,-1765.11) pad.2@776.34,-1701.53 ; pad.2@780.96,-1670.31 cw(c819.71,-1696.21) 819.71,-1649.61 cw(c819.71,-1603) pad.2@780.96,-1628.9 ; D4.2@824.76,-1826.9 ccw(c788.91,-1862.75) 788.91,-1812.05 ccw(c788.91,-1761.35) D4.2@824.76,-1797.2 ; D4.2@839.61,-1803.78 D4.2@839.61,-1812.05 782.04,-1812.05 750,-1780.01 pad.2@750,-1649.61 819.71,-1649.61 864.28,-1694.17 ; R9.2@900.86,-1709.76 ccw(c864.28,-1744.89) 864.28,-1694.17 ; R9.2@900.86,-1678.59 cw(c864.28,-1643.45) 864.28,-1694.17 ; DRIVERC.8@904.09,-1390.17 904.09,-1463.16 1007.89,-1566.96 1007.89,-1671.57 985.29,-1694.17 R9.2@917.09,-1694.17 864.28,-1694.17 ; R9.2@933,-1710.08 cw(c971.41,-1748.49) 971.41,-1694.17 cw(c971.41,-1639.85) R9.2@933,-1678.26
  Bottom Layer w20: R11.2@739.61,-1812.05 D4.2@839.61,-1812.05 ; R11.2@750.21,-1822.65 cw(c775.82,-1848.26) 775.82,-1812.05 cw(c775.82,-1775.83) R11.2@750.21,-1801.44 ; D4.2@824.76,-1826.9 ccw(c788.91,-1862.75) 788.91,-1812.05 ccw(c788.91,-1761.35) D4.2@824.76,-1797.2
DRIVERD: D8.2 DRIVERD.8 pad.4 R21.2 R28.2 | length 1641.6
  Top Layer w20: DRIVERD.8@1640.94,-1391.16 1640.94,-1444.82 1680.28,-1484.16 1778.28,-1484.16 1800,-1505.88 pad.4@1800,-1649.61 ; pad.4@1773.66,-1701.53 cw(c1710.09,-1765.11) 1800,-1765.11 cw(c1889.92,-1765.11) pad.4@1826.34,-1701.53 ; pad.4@1773.66,-1597.68 ccw(c1710.09,-1534.1) 1800,-1534.1 ccw(c1889.92,-1534.1) pad.4@1826.34,-1597.68 ; pad.4@1821.07,-1649.61 ccw(c1821.07,-1545.95) R28.2@1894.37,-1619.25 ; pad.4@1826.34,-1675.94 cw(c1889.92,-1739.52) 1889.92,-1649.61 cw(c1889.92,-1559.69) pad.4@1826.34,-1623.27 ; 1869.36,-1649.61 ccw(c1869.36,-1594.24) R28.2@1908.51,-1633.39 ; D8.2@1885.3,-1822.05 ccw(c1849.45,-1857.9) 1849.45,-1807.2 ccw(c1849.45,-1756.51) D8.2@1885.3,-1792.35 ; D8.2@1910.28,-1797.08 D8.2@1900.15,-1807.2 1830.77,-1807.2 1800,-1776.43 pad.4@1800,-1649.61 ; R28.2@1910.28,-1635.16 1895.83,-1649.61 pad.4@1800,-1649.61
  Bottom Layer w20: R21.2@1776.06,-1813.07 D8.2@1900.15,-1813.07 ; R21.2@1785.75,-1791.6 ccw(c1837.59,-1739.76) 1837.59,-1813.07 ; 1835.29,-1813.07 ccw(c1835.29,-1742.34) D8.2@1885.3,-1792.35 ; 1863.61,-1813.07 cw(c1863.61,-1843.74) D8.2@1885.3,-1822.05
GND: C13.2 C14.2 C15.2 C17.2 C25.2 C32.2 C33.2 C34.2 C37.2 C38.2 C39.1 C40.2 C41.2 C42.2 C44.2 C45.2 C46.2 C47.2 DRIVERA.11 DRIVERA.12 DRIVERA.19 DRIVERA.20 DRIVERB.11 DRIVERB.12 DRIVERB.19 DRIVERB.20 DRIVERC.11 DRIVERC.12 DRIVERC.19 DRIVERC.20 DRIVERD.11 DRIVERD.12 DRIVERD.19 DRIVERD.20 E3.2 E12.2 E19.2 E20.2 E21.2 J5.4 L2.2 R46.1 R47.2 R53.1 R56.1 U1.7 U2.4 | length 3279.6
  Top Layer w20: U1.7@97.09,-834.17 97.09,-896.97 99.29,-899.17 135.26,-899.17 164.28,-870.16 v1(164.28,-836.16) ; DRIVERB.11@146.94,-572.85 146.94,-623.82 167.28,-644.16 176.28,-644.16 185.28,-644.16 196.94,-632.5 DRIVERB.12@196.94,-572.85 ; v1(514.28,-981.16) 514.28,-1032.16 535.28,-1053.16 542.28,-1053.16 ; DRIVERB.19@546.94,-572.85 546.94,-536.5 555.28,-528.16 ; DRIVERB.19@548.27,-546.52 cw(c590.27,-585.38) 590.27,-528.16 ; DRIVERB.19@548.75,-545.19 cw(c571.12,-544) 555.28,-528.16 ; 550.93,-1044.5 ccw(c540.23,-1033.79) DRIVERC.20@552.61,-1025.07 ; DRIVERC.20@554.09,-996.47 554.09,-1041.35 542.28,-1053.16 ; C15.2@586.33,-647.55 ccw(c560.72,-621.94) 596.94,-621.94 ccw(c633.15,-621.94) C15.2@607.54,-647.55 ; 586.44,-524.32 cw(c565.47,-545.29) DRIVERB.20@595.13,-545.29 ; DRIVERB.20@595.57,-546.48 ccw(c555.28,-581.62) 555.28,-528.16 ; v1(596.94,-658.16) DRIVERB.20@596.94,-572.85 596.94,-534.82 590.28,-528.16 ; DRIVERC.19@604.09,-996.47 604.09,-1047.35 598.28,-1053.16 542.28,-1053.16 ; DRIVERC.12@954.09,-996.47 954.09,-951.35 979.28,-926.16 v1@1027.09,-926.16 ; DRIVERC.12@955.9,-968.91 cw(c1002.67,-968.91) 969.6,-935.84 ; v1@992.82,-631.62 ccw(c963.04,-601.84) DRIVERA.11@1005.13,-600.48 ; DRIVERC.11@1004.09,-996.47 1004.09,-949.16 v1@1027.09,-926.16 ; DRIVERC.11@1005.9,-968.91 cw(c1057.96,-968.91) v1@1021.15,-932.1 ; DRIVERA.11@1006.94,-572.86 1006.94,-617.5 v1(984.28,-640.16) 1030.94,-640.16 1056.94,-614.16 DRIVERA.12@1056.94,-572.86 ; v1(1038.28,-926.16) v1@1027.09,-926.16 ; 1044.13,-626.96 ccw(c1017.58,-600.42) DRIVERA.12@1055.13,-600.42 ; v1(1241.28,-1075.01) 1277.28,-1075.01 ; DRIVERD.20@1290.94,-997.46 1290.94,-1061.35 1277.28,-1075.01 ; DRIVERD.19@1340.94,-997.46 1340.94,-1063.35 1329.28,-1075.01 1277.28,-1075.01 ; DRIVERA.19@1406.94,-572.86 1406.94,-617.82 1413.28,-624.16 1449.28,-624.16 1456.94,-616.5 ; C34.2@1444.33,-663.55 ccw(c1413.9,-633.12) 1456.94,-633.12 ; C34.2@1454.94,-674.16 v1(1456.94,-672.16) 1456.94,-616.5 ; 1456.94,-642.77 ccw(c1486.32,-642.77) C34.2@1465.54,-663.55 ; DRIVERA.20@1456.94,-572.86 1456.94,-616.5 ; DRIVERD.12@1690.94,-997.46 1690.94,-1059.82 v1(1716.28,-1085.16) 1740.94,-1060.5 DRIVERD.11@1740.94,-997.46 ; R53.1@2328.17,-427.04 ccw(c2302.57,-452.65) 2302.57,-416.43 ccw(c2302.57,-380.22) R53.1@2328.17,-405.83 ; U2.4@2333.94,-485.16 2279.28,-485.16 2268.28,-474.16 2268.28,-436.16 2288,-416.43 v1(2338.78,-416.43) ; C40.2@2380.28,-295.01 L2.2@2500.94,-295.01 ; C40.2@2390.88,-305.61 cw(c2416.49,-331.22) 2416.49,-295.01 cw(c2416.49,-258.79) C40.2@2390.88,-284.4 ; 2406.1,-295.01 ccw(c2406.1,-213.86) L2.2@2463.48,-271.24 ; 2420.59,-295.01 cw(c2420.59,-355.67) L2.2@2463.48,-312.78 ; L2.2@2500.79,-295.16 L2.2@2500.94,-295.01 ; v1(2503.94,-292.01) L2.2@2500.94,-295.01 ; 555.28,-528.16 590.28,-528.16
  Top Layer w40: E21.2@-390.35,-1265.63 E21.2@-375.82,-1265.63 ; E21.2@-381.52,-1256.79 ccw(c-346.83,-1222.11) -346.83,-1271.16 ; E21.2@-375.82,-1271.16 C44.2@-209.72,-1271.16 ; C44.2@-209.72,-1275.16 -208.74,-1274.17 v1(-82.91,-1274.17) R56.1@-2.91,-1274.17
  other v1: 117.05,-1035.59 1210.28,-949.49 2013.94,-780.16 1228.94,-758.16 672.22,-754.44 176.28,-642.16 -271.72,-426.01 57.09,-414.17 1926.09,-405.17
GND1: C30.2 C35.2 D5.2 D7.1 D9.1 DRIVERA.4 E14.2 E17.1 E18.1 pad.10 R20.1 R22.2 | length 989.7
  Top Layer w20: pad.10@723.66,51.93 ccw(c660.09,115.51) 750,115.51 ccw(c839.92,115.51) pad.10@776.34,51.93 ; D7.1@735.43,189.99 cw(c700.24,154.81) 750,154.81 ; D7.1@735.43,219.69 ccw(c699.58,255.54) 750.28,255.54 ccw(c800.97,255.54) D7.1@765.13,219.69 ; D5.2@735.43,309.99 cw(c699.58,274.14) 750.28,274.14 cw(c800.97,274.14) D5.2@765.13,309.99 ; E18.1@750,-180.75 v1(771.61,-202.36) ; pad.10@750,0 D7.1@750,204.84 ; 750,153.48 cw(c801.64,153.48) D7.1@765.13,189.99 ; D7.1@750.28,204.84 D5.2@750.28,324.84 ; DRIVERA.4@1306.94,-179.16 1306.94,17.84 v1(1313.94,24.84) ; 1306.94,-28.27 cw(c1367.05,-28.27) C35.2@1324.54,14.24
GND2: C7.2 C16.2 D1.1 D3.1 DRIVERB.4 E4.2 E6.1 E7.1 pad.12 R1.2 R10.1 | length 689.1
  Top Layer w20: D3.1@-79.91,197.83 -33.83,197.83 ; D3.1@-64.06,184.05 cw(c-33.84,157.78) -33.84,197.83 ; D3.1@-64.06,211.6 ccw(c-33.84,237.87) -33.84,197.83 ; pad.12@-26.34,51.93 ccw(c-89.91,115.51) 0,115.51 ccw(c89.92,115.51) pad.12@26.34,51.93 ; pad.12@0,0 0,163.99 -33.83,197.83 ; C16.2@437.28,-20.16 C16.2@437.94,-20.82 ; C16.2@437.48,-26.78 cw(c414.65,-49.61) 446.94,-49.61 ; 446.94,-55.16 cw(c487.08,-55.16) C16.2@458.69,-26.78 ; C16.2@446.94,-18.82 DRIVERB.4@446.94,-179.15 DRIVERB.4@449.28,-181.5
  other v1: -98.98,-174.53 448.09,-16.17
GND3: C12.2 C18.2 D2.1 D4.1 DRIVERC.4 E5.2 E8.1 E9.1 pad.1@600,-1649.61 R2.2 R11.1 | length 1368
  Top Layer w20: D4.1@539.61,-1812.05 576.39,-1812.05 ; D4.1@540.13,-1811.2 ccw(c558.04,-1782.22) 582.13,-1806.31 ; D4.1@550.65,-1794.18 ccw(c571.69,-1760.13) 600,-1788.43 ; D4.1@557.69,-1822.72 cw(c576.38,-1833.75) 576.38,-1812.05 ; D4.1@557.69,-1801.37 ccw(c576.38,-1790.34) 576.38,-1812.05 ; pad.1@573.66,-1701.53 cw(c510.09,-1765.11) 600,-1765.11 cw(c689.92,-1765.11) pad.1@626.34,-1701.53 ; pad.1@614.19,-1614.22 cw(c643.31,-1594.14) 618.3,-1569.13 ; pad.1@630.66,-1602.87 cw(c663.4,-1580.28) 635.27,-1552.16 ; 634.28,-1552.16 635.28,-1552.16 ; DRIVERC.4@704.09,-1390.17 704.09,-1531.35 683.28,-1552.16 635.28,-1552.16 ; 576.39,-1812.05 600,-1788.43 ; 600,-1788.43 pad.1@600,-1649.61 602.28,-1647.33 602.28,-1585.16 635.28,-1552.16
  Top Layer w40: C18.2@490.28,-1615.16 570.1,-1615.16 pad.1@602.28,-1647.33 ; C18.2@512.84,-1615.16 cw(c512.84,-1711.17) pad.1@580.74,-1643.28
  Bottom Layer w20: D4.1@539.61,-1812.05 599.88,-1812.05 ; D4.1@554.46,-1826.9 cw(c590.31,-1862.75) 590.31,-1812.05 cw(c590.31,-1761.35) D4.1@554.46,-1797.2 ; 600,-1811.93 599.88,-1812.05 ; R11.1@629,-1822.65 ccw(c603.39,-1848.26) 603.39,-1812.05 ccw(c603.39,-1775.83) R11.1@629,-1801.44 ; R11.1@639.61,-1812.05 599.88,-1812.05
GND4: C31.2 C36.2 D6.2 D8.1 D10.1 DRIVERD.4 E13.2 E15.1 E16.1 pad.3@1650,-1649.61 R21.1 R29.2 | length 2101.5
  Top Layer w20: DRIVERD.4@1440.94,-1391.16 1440.94,-1454.67 1451.28,-1465.01 1481.28,-1465.01 1493.94,-1477.67 C36.2@1493.94,-1535.16 1493.94,-1612.27 1531.28,-1649.61 pad.3@1650,-1649.61 ; C36.2@1483.33,-1545.76 cw(c1457.72,-1571.37) 1493.94,-1571.37 cw(c1530.15,-1571.37) C36.2@1504.54,-1545.76 ; C36.2@1483.33,-1524.55 ccw(c1457.72,-1498.94) 1493.94,-1498.94 ccw(c1530.15,-1498.94) C36.2@1504.54,-1524.55 ; D8.1@1600.15,-1807.2 1636.26,-1807.2 ; D8.1@1618.4,-1817.59 cw(c1636.26,-1827.75) 1636.26,-1807.2 ; D8.1@1618.4,-1796.82 ccw(c1636.26,-1786.65) 1636.26,-1807.2 ; pad.3@1623.66,-1701.53 cw(c1560.09,-1765.11) 1650,-1765.11 cw(c1739.92,-1765.11) pad.3@1676.34,-1701.53 ; pad.3@1623.66,-1675.94 ccw(c1560.09,-1739.52) 1560.09,-1649.61 ccw(c1560.09,-1559.69) pad.3@1623.66,-1623.27 ; pad.3@1641.14,-1658.46 pad.3@1650,-1649.61 ; 1636.26,-1807.2 1650,-1793.46 pad.3@1650,-1649.61
  Bottom Layer w20: D6.2@1199.09,-1820.31 ccw(c1162.42,-1783.64) 1214.28,-1783.64 ; D6.2@1213.94,-1835.16 1214.28,-1834.82 1214.28,-1687.2 1251.87,-1649.61 1491.28,-1649.61 ; 1214.28,-1785.28 ccw(c1263.82,-1785.28) D6.2@1228.79,-1820.31 ; 1492.28,-1649.61 pad.3@1650,-1649.61 ; D8.1@1600.15,-1807.2 1670.15,-1807.2 R21.1@1675.15,-1802.2 ; D8.1@1615,-1822.05 cw(c1650.85,-1857.9) 1650.85,-1807.2 cw(c1650.85,-1756.51) D8.1@1615,-1792.35 ; pad.3@1623.66,-1675.94 ccw(c1560.09,-1739.52) 1560.09,-1649.61 ccw(c1560.09,-1559.69) pad.3@1623.66,-1623.27 ; D8.1@1626.86,-1807.2 ccw(c1626.86,-1753.92) R21.1@1664.54,-1791.6
IPM1: J5.3 R42.1 U1.5 | length 836.9
  Top Layer w20: J5.3@-422.91,-814.17 -320.55,-814.17 -270.56,-764.17 -25.12,-764.17 -2.91,-786.38 U1.5@-2.91,-834.17 -1.72,-835.36 R42.1@-1.72,-995.01 ; J5.3@-389.06,-829.02 cw(c-353.21,-864.87) -353.21,-814.17 cw(c-353.21,-763.47) J5.3@-389.06,-799.32 ; -20.32,-768.97 cw(c-57.53,-806.17) U1.5@-4.91,-806.17 ; R42.1@-12.33,-984.4 ccw(c-37.94,-958.79) -1.72,-958.79 ccw(c34.49,-958.79) R42.1@8.88,-984.4
IPM1*: C41.1 DRIVERA.14 DRIVERB.13 DRIVERC.14 DRIVERD.13 R44.2 R46.2 | length 3438.3
  Top Layer w20: R46.2@206.45,-1024.98 ccw(c180.84,-999.35) 217.07,-999.37 ; R44.2@206.48,-964.77 cw(c180.86,-990.37) 217.07,-990.39 cw(c253.28,-990.4) R44.2@227.69,-964.78 ; R46.2@217.05,-1045.39 v1(217.05,-1035.59) ; v1(217.05,-1035.59) R44.2@217.09,-954.17 ; v1(217.05,-1035.59) 272.82,-1035.55 293.6,-1014.77 293.6,-826.68 246.94,-780.02 DRIVERB.13@246.94,-591.16 ; 217.07,-999.39 ccw(c253.27,-999.4) 227.66,-1024.99 ccw(c253.17,-999.47) 253.17,-1035.55 ; R46.2@227.65,-1046.2 cw(c253.36,-1071.9) 253.36,-1035.55 ; v1(821.28,-1116.01) 854.09,-1083.2 DRIVERC.14@854.09,-996.47 854.09,-746.35 879.28,-721.16 1131.28,-721.16 1156.94,-695.5 DRIVERA.14@1156.94,-572.86 ; v2(1612.68,-1142.79) 1640.94,-1114.53 DRIVERD.13@1640.94,-997.46
  Bottom Layer w20: C41.1@206.44,-1046.2 cw(c180.83,-1071.8) 217.05,-1071.8 cw(c253.26,-1071.8) C41.1@227.65,-1046.2 ; v1(217.05,-1035.59) 217.05,-1134.24 256.28,-1173.47 763.82,-1173.47 ; v1(821.28,-1116.01) 763.82,-1173.47 ; v2(1612.68,-1142.79) 1608.74,-1142.79 1578.07,-1173.47 763.82,-1173.47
